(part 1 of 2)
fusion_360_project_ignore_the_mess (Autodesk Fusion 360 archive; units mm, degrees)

design "carcasa pantallita" references "ESP32-C3 supermini v5"
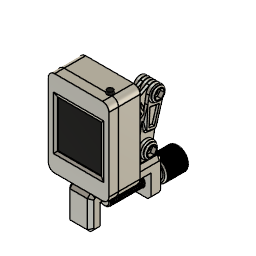
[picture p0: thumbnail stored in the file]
sketch "pantalla frente" plane through (0, 0, 0) normal (0, 1, 0) x axis (1, 0, 0)
  line L1 (29.45, 0) -> (0, 0)
  line L2 (29.45, -37.15) -> (29.45, 0)
  line L3 (0, -37.15) -> (29.45, -37.15)
  line L4 (0, 0) -> (0, -37.15)
  line L5 (28.45, -35.55) -> (1, -35.55)
  line L6 (28.45, -6.2) -> (28.45, -35.55)
  line L7 (1, -6.2) -> (28.45, -6.2)
  line L8 (1, -35.55) -> (1, -6.2)
  line L9 (30.7, -41.25) -> (-0.9, -41.25)
  line L10 (30.7, 3.05) -> (30.7, -41.25)
  line L11 (-0.9, 3.05) -> (30.7, 3.05)
  line L12 (-0.9, -41.25) -> (-0.9, 3.05)
  line L13 (14.9, -37.15) -> (14.9, -41.25)
  circle C1 centre (28.75, -39.5) radius 1.1
  circle C2 centre (1.05, -39.5) radius 1.1
  point P1 (0, 0)
  point P2 (0, 0)
  point P15 (14.9, -41.25)
  point P16 (14.9, -37.15)
  point P4 (29.45, -37.15)
  point P5 (0, -37.15)
  point P10 (-0.9, -41.25)
  point P11 (30.7, -41.25)
  point P13 (-0.9, 3.05)
  point P14 (28.75, -39.5)
  horizontal L1
  vertical L2
  horizontal L3
  vertical L4
  coincident P1 P2
  horizontal L5
  vertical L6
  horizontal L7
  vertical L8
  horizontal L9
  vertical L10
  horizontal L11
  vertical L12
  midpoint L9 P15
  coincident L3 P16
  perpendicular L3 L13
  symmetric C1 L13 C2
  dimension "d1" distance P4 P5 = 29.45
  dimension "d2" distance P2 P5 = 37.15
  dimension "d3" distance L3 L5 = 1.6
  dimension "d4" distance L2 L6 = 1
  dimension "d5" distance L4 L8 = 1
  dimension "d6" distance L1 L7 = 6.2
  dimension "d7" distance P10 P11 = 31.6
  dimension "d8" distance P10 P13 = 44.3
  dimension "d9" distance L3 L9 = 4.1
  dimension "d10" distance L4 L12 = 0.9
  dimension "d11" distance L9 P14 = 1.75 (= "1.1 mm + 0.65 mm")
  dimension "d12" distance L10 P14 = 1.95 (= "1.1 mm + 0.85 mm")
  dimension "d13" diameter C1 = 2.2
sketch "pantalla atras" plane through (0, 0, 0) normal (0, 1, 0) x axis (1, 0, 0)
  line L1 (30.7, -41.25) -> (-0.9, -41.25)
  line L2 (30.7, 3.05) -> (30.7, -41.25)
  line L3 (-0.9, -41.25) -> (-0.9, 3.05)
  line L4 (-0.9, 3.05) -> (30.7, 3.05)
  line L5 (14.15, -17.05) -> (1.2, -17.05)
  line L6 (14.15, -7.75) -> (14.15, -17.05)
  line L7 (1.2, -7.75) -> (14.15, -7.75)
  line L8 (1.2, -17.05) -> (1.2, -7.75)
  line L9 (0.6, 0.15) -> (28.8, 0.15)
  line L10 (0.6, 2.65) -> (0.6, 0.15)
  line L11 (28.8, 2.65) -> (0.6, 2.65)
  line L12 (28.8, 0.15) -> (28.8, 2.65)
  circle C1 centre (28.75, -39.5) radius 1.1
  circle C2 centre (1.05, -39.5) radius 1.1
  point P8 (1.2, -17.05)
  point P9 (14.15, -17.05)
  horizontal L5
  vertical L6
  horizontal L7
  vertical L8
  horizontal L9
  vertical L10
  horizontal L11
  vertical L12
  dimension "d14" distance L3 L8 = 2.1
  dimension "d15" distance P8 P9 = 12.95
  dimension "d16" distance L5 L7 = 9.3
  dimension "d17" distance L1 L5 = 24.2
  dimension "d18" distance L3 L10 = 1.5
  dimension "d19" distance L2 L12 = 1.9
  dimension "d20" distance L4 L11 = 0.4
  dimension "d21" distance L9 L11 = 2.5
extrude "Extrude1" new body sketch "pantalla frente" profile of L1 L2 L3 L4 L5 L6 L7 L8 L9 L10 L11 L12 C1 C2 along normal blind 1.65
extrude "Extrude2" add sketch "pantalla frente" profile of L1 L2 L3 L4 L5 L6 L7 L8 against normal blind 3.3
extrude "Extrude3" sketch "pantalla frente" profile of L5 L6 L7 L8 blind 0.01
extrude "Extrude4" sketch "pantalla atras" profile of L5 L6 L7 L8 blind 2.6
extrude "Extrude5" sketch "pantalla atras" profile of L9 L10 L11 L12 blind 2.4
sketch "cover frente" plane through (0, 0, 0) normal (0, 1, 0) x axis (1, 0, 0)
  line L1 (-4.25, -47.8) -> (33.7, -47.8)
  line L2 (-4.25, 6.05) -> (-4.25, -47.8)
  line L3 (33.7, 6.05) -> (-4.25, 6.05)
  line L4 (33.7, -47.8) -> (33.7, 6.05)
  line L5 (30.7, -41.25) -> (-0.9, -41.25)
  line L6 (30.7, 3.05) -> (30.7, -41.25)
  line L7 (-0.9, 3.05) -> (30.7, 3.05)
  line L8 (-0.9, -41.25) -> (-0.9, 3.05)
  line L9 (1, -35.55) -> (1, -6.2)
  line L10 (28.45, -35.55) -> (1, -35.55)
  line L11 (1, -6.2) -> (28.45, -6.2)
  line L12 (28.45, -6.2) -> (28.45, -35.55)
  horizontal L1
  vertical L2
  horizontal L3
  vertical L4
  dimension "d35" distance L4 L6 = 3
  dimension "d37" distance L3 L7 = 3
  dimension "d39" distance L1 L10 = 12.25
  dimension "d40" distance L2 L9 = 5.25
extrude "Extrude6" sketch "cover frente" profile of L1 L2 L3 L4 L9 L10 L11 L12 to an object from offset -1
combine "Combine1"
offset_faces "OffsetFaces1" distance -0.2
offset_faces "OffsetFaces2" distance -0.2
offset_faces "OffsetFaces3" distance -0.2
offset_faces "OffsetFaces4" distance -0.2
offset_faces "OffsetFaces5" distance -0.2
offset_faces "OffsetFaces6" distance -0.2
chamfer "Chamfer1" distance 0.6 distance 2
sketch "Sketch5" plane through (0, 0, 0) normal (0, 1, 0) x axis (1, 0, 0)
  line L1 (-4.25, -47.8) -> (33.7, -47.8)
  line L2 (33.7, -47.8) -> (33.7, 6.05)
  line L3 (-4.25, 6.05) -> (-4.25, -47.8)
  line L4 (33.7, 6.05) -> (-4.25, 6.05)
  line L5 (-4.25, -5.95) -> (33.7, -5.95)
  line L6 (30.9, -41.45) -> (30.9, 3.25)
  line L7 (-1.1, -41.45) -> (30.9, -41.45)
  line L8 (-1.1, 3.25) -> (-1.1, -41.45)
  line L9 (30.9, 3.25) -> (-1.1, 3.25)
  point P6 (33.7, -5.95)
  point P7 (-4.25, -5.95)
  point P8 (30.7, 3.05)
  coincident L2 P6
  coincident L3 P7
  perpendicular L3 L5
  dimension "d52" distance L5 P8 = 9
extrude "Extrude7" sketch "Sketch5" to an object offset 3
extrude "Extrude8" cut sketch "Sketch5" profile of L5 L6 L7 L8 L9 to an object offset -1
extrude "Extrude9" add of existing geometry blind 14 from offset 8
sketch "Sketch6" plane through (0, 1.65, 0) normal (0, -1, 0) x axis (1, 0, 0)
  line L1 (30.9, -3.25) -> (30.9, 19.45)
  line L2 (-1.1, -3.25) -> (30.9, -3.25)
  line L3 (-1.1, 19.45) -> (-1.1, -3.25)
  line L4 (30.9, 19.45) -> (-1.1, 19.45)
  line L5 (-1.1, 33.45) -> (30.9, 33.45)
  line L6 (-1.1, 41.45) -> (-1.1, 33.45)
  line L7 (30.9, 41.45) -> (-1.1, 41.45)
  line L8 (30.9, 33.45) -> (30.9, 41.45)
  line L9 (-4.25, -6.05) -> (-4.25, 47.8)
  line L10 (33.7, -6.05) -> (-4.25, -6.05)
  line L11 (33.7, 47.8) -> (33.7, -6.05)
  line L12 (-4.25, 47.8) -> (33.7, 47.8)
  line L13 (30.9, 19.45) -> (30.9, 33.45)
  line L14 (-1.1, 19.45) -> (-1.1, 33.45)
  line L15 (8.9, 19.45) -> (8.9, 33.45)
  line L16 (20.9, 19.45) -> (20.9, 33.45)
  line L17 (32.9, -5.25) -> (-3.45, -5.25)
  line L18 (32.9, 47) -> (32.9, -5.25)
  line L19 (-3.45, 47) -> (32.9, 47)
  line L20 (-3.45, -5.25) -> (-3.45, 47)
  point P6 (30.9, 33.45)
  point P14 (30.9, 33.45)
  point P2 (30.9, 19.45)
  point P15 (30.9, 19.45)
  point P7 (-1.1, 33.45)
  point P16 (-1.1, 33.45)
  point P5 (-1.1, 19.45)
  point P17 (-1.1, 19.45)
  point P18 (8.9, 33.45)
  point P19 (8.9, 19.45)
  point P20 (20.9, 33.45)
  point P21 (20.9, 19.45)
  coincident P6 P14
  coincident P2 P15
  coincident P7 P16
  coincident P5 P17
  coincident L5 P18
  coincident L4 P19
  perpendicular L4 L15
  coincident L5 P20
  coincident L4 P21
  perpendicular L4 L16
  dimension "d71" distance L13 L16 = 10
  dimension "d72" distance L14 L15 = 10
  dimension "d77" = -0.8
extrude "Extrude10" cut sketch "Sketch6" profile of L4 L5 L13 L14 against normal blind 0.2
extrude "Extrude11" cut of existing geometry blind -0.925 (= "( -1.65 / 2 ) * 1 mm - 0.1 mm")
extrude "Extrude12" new body of existing geometry to an object
combine "Combine2"
combine "Combine3"
offset_faces "OffsetFaces7" distance -0.1
chamfer "Chamfer2" distance 2 distance 2
extrude "Extrude13" cut sketch "Sketch6" profile of L4 L5 L15 L16 to an object
chamfer "Chamfer3" distance 0.4 distance 1
extrude "Extrude14" add sketch "Sketch6" profile of L1 L2 L3 L6 L7 L8 L13 L14 L17 L18 L19 L20 along normal blind 1.4
fillet "Fillet3" radius 4
combine "Combine4"
offset_faces "OffsetFaces8" distance -0.1
offset_faces "OffsetFaces9" distance -0.1
fillet "Fillet4" radius 4
sketch "Sketch7" plane through (0, 7.05, 0) normal (0, 1, 0) x axis (-1, 0, 0)
  line L1 (4.25, 43.8) -> (4.25, -2.05)
  line L2 (-29.7, 47.8) -> (0.25, 47.8)
  line L3 (-33.7, -2.05) -> (-33.7, 43.8)
  line L4 (0.25, -6.05) -> (-29.7, -6.05)
  line L5 (4.25, 20.875) -> (-33.7, 20.875)
  line L6 (-14.725, 20.875) -> (-14.725, 47.8)
  line L7 (-14.725, -6.05) -> (-14.725, 20.875)
  line L8 (4.25, 17.875) -> (-33.7, 17.875)
  line L9 (4.25, 23.875) -> (-33.7, 23.875)
  line L10 (-11.725, 47.8) -> (-11.725, -6.05)
  line L11 (-17.725, -6.05) -> (-17.725, 47.8)
  arc A1 centre (0.25, -2.05) radius 4 clockwise from (4.25, -2.05) to (0.25, -6.05)
  arc A2 centre (0.25, 43.8) radius 4 clockwise from (0.25, 47.8) to (4.25, 43.8)
  arc A3 centre (-29.7, 43.8) radius 4 clockwise from (-33.7, 43.8) to (-29.7, 47.8)
  arc A4 centre (-29.7, -2.05) radius 4 clockwise from (-29.7, -6.05) to (-33.7, -2.05)
  circle C1 centre (-14.725, 20.875) radius 3
  circle C2 centre (-14.725, 20.875) radius 9
  circle C3 centre (-14.725, 20.875) radius 12
  circle C4 centre (-14.725, 20.875) radius 10.5
  arc A5 centre (-10.225, 30.3618) radius 1.5 clockwise from (-10.8679, 29.0066) to (-9.5821, 31.7171)
  arc A6 centre (-5.2382, 25.375) radius 1.5 clockwise from (-3.8829, 26.0179) to (-6.5934, 24.7321)
  arc A7 centre (-19.225, 30.3618) radius 1.5 clockwise from (-19.8679, 31.7171) to (-18.5821, 29.0066)
  arc A8 centre (-5.2382, 16.375) radius 1.5 clockwise from (-6.5934, 17.0179) to (-3.8829, 15.7321)
  arc A9 centre (-24.2118, 16.375) radius 1.5 clockwise from (-25.5671, 15.7321) to (-22.8566, 17.0179)
  arc A10 centre (-24.2118, 25.375) radius 1.5 clockwise from (-22.8566, 24.7321) to (-25.5671, 26.0179)
  arc A11 centre (-19.225, 11.3882) radius 1.5 clockwise from (-18.5821, 12.7434) to (-19.8679, 10.0329)
  arc A12 centre (-10.225, 11.3882) radius 1.5 clockwise from (-9.5821, 10.0329) to (-10.8679, 12.7434)
  circle C5 centre (-14.725, 20.875) radius 7
  circle C6 centre (-14.725, 20.875) radius 14
  point P14 (-33.7, 20.875)
  point P15 (4.25, 20.875)
  point P16 (-14.725, 47.8)
  point P17 (-14.725, 20.875)
  point P18 (-14.725, -6.05)
  point P19 (-14.725, 20.875)
  point P20 (-14.725, 20.875)
  point P22 (-33.7, 17.875)
  point P23 (4.25, 17.875)
  point P24 (-33.7, 23.875)
  point P25 (4.25, 23.875)
  point P26 (-11.725, -6.05)
  point P27 (-11.725, 47.8)
  point P28 (-17.725, 47.8)
  point P29 (-17.725, -6.05)
  point P34 (-9.5821, 31.7171)
  point P35 (-10.8679, 29.0066)
  point P36 (-3.8829, 26.0179)
  point P37 (-6.5934, 24.7321)
  point P38 (-19.8679, 31.7171)
  point P39 (-18.5821, 29.0066)
  point P41 (-6.5934, 17.0179)
  point P42 (-3.8829, 15.7321)
  point P48 (-25.5671, 26.0179)
  point P47 (-22.8566, 24.7321)
  point P45 (-22.8566, 17.0179)
  point P44 (-25.5671, 15.7321)
  point P53 (-9.5821, 10.0329)
  point P54 (-10.8679, 12.7434)
  point P51 (-19.8679, 10.0329)
  point P50 (-18.5821, 12.7434)
  midpoint L3 P14
  midpoint L1 P15
  midpoint L2 P16
  midpoint L5 P17
  midpoint L4 P18
  coincident P17 P19
  coincident P17 P20
  concentric C2 C3
  coincident L3 P22
  coincident L1 P23
  perpendicular L1 L8
  coincident L3 P24
  coincident L1 P25
  perpendicular L1 L9
  coincident L4 P26
  coincident L2 P27
  perpendicular L2 L10
  coincident L2 P28
  coincident L4 P29
  perpendicular L4 L11
  concentric C1 C4
  tangent C3 A6
  tangent L9 A6
  tangent C2 A5
  tangent C2 A7
  tangent L11 A7
  tangent L10 A5
  coincident C3 P34
  coincident C2 P35
  coincident C3 P36
  coincident C2 P37
  coincident C3 P38
  coincident C2 P39
  tangent C3 A8
  tangent L8 A8
  coincident C2 P41
  coincident C3 P42
  symmetric L7 P36 P48
  symmetric L7 A6 A10
  symmetric L7 P37 P47
  symmetric L7 P41 P45
  symmetric L7 A8 A9
  symmetric L7 P42 P44
  symmetric L5 P34 P53
  symmetric L5 A5 A12
  symmetric L5 P35 P54
  symmetric L5 P38 P51
  symmetric L5 A7 A11
  symmetric L5 P39 P50
  concentric C3 C5
  concentric C3 C6
  dimension "d90" diameter C1 = 6
  dimension "d95" diameter C2 = 18
  dimension "d96" diameter C3 = 24
  dimension "d97" distance L5 L9 = 3
  dimension "d98" distance L5 L8 = 3
  dimension "d99" distance L7 L11 = 3
  dimension "d100" distance L7 L10 = 3
  dimension "d101" diameter C4 = 21
  dimension "d104" diameter C5 = 14
  dimension "d105" diameter C6 = 28
extrude "Extrude15" cut sketch "Sketch7" profile of C1 to an object
fillet "Fillet5" radius 0.4
extrude "Extrude16" cut sketch "Sketch7" profile of C2 C3 A6 A5 A7 A8 A9 A10 A11 A12 to an object
extrude "Extrude17" sketch "Sketch7" profile of C2 C3 L8 L9 L10 L11 A6 A5 A7 A8 A9 A10 A11 A12 C5 C6 to an object
delete_face "DeleteFace1"
delete_face "DeleteFace2"
delete_face "DeleteFace3"
sketch "Sketch8" plane through (0, 7.05, 0) normal (0, 1, 0) x axis (-1, 0, 0)
  line L1 (4.25, 43.8) -> (4.25, -2.05)
  line L2 (-29.7, 47.8) -> (0.25, 47.8)
  line L3 (-33.7, -2.05) -> (-33.7, 43.8)
  line L4 (0.25, -6.05) -> (-29.7, -6.05)
  line L5 (-9.725, 16.875) -> (-19.725, 16.875)
  line L6 (-9.725, 6.875) -> (-9.725, 16.875)
  line L7 (-19.725, 6.875) -> (-9.725, 6.875)
  line L8 (-19.725, 16.875) -> (-19.725, 6.875)
  line L9 (-14.725, 5.875) -> (-14.725, 20.875)
  line L10 (-17.725, 6.875) -> (-17.725, 16.875)
  line L11 (-15.725, 6.875) -> (-15.725, 16.875)
  line L12 (-11.725, 6.875) -> (-11.725, 16.875)
  line L13 (-13.725, 6.875) -> (-13.725, 16.875)
  arc A1 centre (-14.725, 20.875) radius 9 clockwise from (-18.5821, 12.7434) to (-22.8566, 17.0179)
  arc A2 centre (-19.225, 11.3882) radius 1.5 clockwise from (-18.5821, 12.7434) to (-19.8679, 10.0329)
  arc A3 centre (-14.725, 20.875) radius 12 clockwise from (-19.8679, 10.0329) to (-25.5671, 15.7321)
  arc A4 centre (-24.2118, 16.375) radius 1.5 clockwise from (-25.5671, 15.7321) to (-22.8566, 17.0179)
  arc A5 centre (-14.725, 20.875) radius 9 clockwise from (-22.8566, 24.7321) to (-18.5821, 29.0066)
  arc A6 centre (-24.2118, 25.375) radius 1.5 clockwise from (-22.8566, 24.7321) to (-25.5671, 26.0179)
  arc A7 centre (-14.725, 20.875) radius 12 clockwise from (-25.5671, 26.0179) to (-19.8679, 31.7171)
  arc A8 centre (-19.225, 30.3618) radius 1.5 clockwise from (-19.8679, 31.7171) to (-18.5821, 29.0066)
  arc A9 centre (-14.725, 20.875) radius 9 clockwise from (-6.5934, 17.0179) to (-10.8679, 12.7434)
  arc A10 centre (-5.2382, 16.375) radius 1.5 clockwise from (-6.5934, 17.0179) to (-3.8829, 15.7321)
  arc A11 centre (-14.725, 20.875) radius 12 clockwise from (-3.8829, 15.7321) to (-9.5821, 10.0329)
  arc A12 centre (-10.225, 11.3882) radius 1.5 clockwise from (-9.5821, 10.0329) to (-10.8679, 12.7434)
  arc A13 centre (-14.725, 20.875) radius 9 clockwise from (-10.8679, 29.0066) to (-6.5934, 24.7321)
  arc A14 centre (-10.225, 30.3618) radius 1.5 clockwise from (-10.8679, 29.0066) to (-9.5821, 31.7171)
  arc A15 centre (-14.725, 20.875) radius 12 clockwise from (-9.5821, 31.7171) to (-3.8829, 26.0179)
  arc A16 centre (-5.2382, 25.375) radius 1.5 clockwise from (-3.8829, 26.0179) to (-6.5934, 24.7321)
  circle C1 centre (-14.725, 20.875) radius 3
  arc A17 centre (0.25, -2.05) radius 4 clockwise from (4.25, -2.05) to (0.25, -6.05)
  arc A18 centre (0.25, 43.8) radius 4 clockwise from (0.25, 47.8) to (4.25, 43.8)
  arc A19 centre (-29.7, 43.8) radius 4 clockwise from (-33.7, 43.8) to (-29.7, 47.8)
  arc A20 centre (-29.7, -2.05) radius 4 clockwise from (-29.7, -6.05) to (-33.7, -2.05)
  circle C2 centre (-14.725, 20.875) radius 15
  circle C3 centre (-14.725, 20.875) radius 3
  point P4 (-14.725, 20.875)
  point P45 (-14.725, 20.875)
  point P46 (-14.725, 5.875)
  point P47 (-17.725, 16.875)
  point P48 (-17.725, 6.875)
  point P49 (-15.725, 16.875)
  point P50 (-15.725, 6.875)
  point P51 (-11.725, 16.875)
  point P52 (-11.725, 6.875)
  point P53 (-13.725, 16.875)
  point P54 (-13.725, 6.875)
  point P39 (-14.725, 20.875)
  concentric A1 C2
  concentric A1 C3
  horizontal L5
  vertical L6
  horizontal L7
  vertical L8
  coincident P4 P45
  coincident C2 P46
  perpendicular L7 L9
  coincident L5 P47
  coincident L7 P48
  perpendicular L7 L10
  coincident L5 P49
  coincident L7 P50
  perpendicular L5 L11
  coincident L5 P51
  coincident L7 P52
  perpendicular L7 L12
  coincident L5 P53
  coincident L7 P54
  perpendicular L7 L13
  dimension "d109" diameter C2 = 30
  dimension "d110" diameter C3 = 6
  dimension "d111" distance L8 L9 = 5
  dimension "d112" distance L6 L9 = 5
  dimension "d113" distance L5 L7 = 10
  dimension "d114" distance P39 L5 = 4
  dimension "d118" distance L8 L10 = 2
  dimension "d119" distance L10 L11 = 2
  dimension "d120" distance L6 L12 = 2
  dimension "d121" distance L12 L13 = 2
extrude "Extrude18" new body sketch "Sketch8" profile of A1 A2 A9 A12 L5 L6 L7 L8 L10 L11 L12 L13 blind 10 from offset 2 bodies "mount"
sketch "Sketch9" plane through (19.725, 0, 0) normal (1, 0, 0) x axis (0, 1, 0)
  line L1 (9.05, 6.875) -> (9.05, 16.875)
  line L2 (19.05, 6.875) -> (9.05, 6.875)
  line L3 (19.05, 16.875) -> (19.05, 6.875)
  line L4 (9.05, 16.875) -> (19.05, 16.875)
  line L5 (19.05, 6.875) -> (9.05, 16.875)
  line L6 (19.05, 16.875) -> (9.05, 6.875)
  line L7 (14.05, 15.0504) -> (16.8, 13.4627)
  line L8 (11.3, 13.4627) -> (14.05, 15.0504)
  line L9 (11.3, 10.2873) -> (11.3, 13.4627)
  line L10 (14.05, 8.6996) -> (11.3, 10.2873)
  line L11 (16.8, 10.2873) -> (14.05, 8.6996)
  line L12 (16.8, 13.4627) -> (16.8, 10.2873)
  circle C1 centre (14.05, 11.875) radius 1.65
  circle C2 centre (14.05, 11.875) radius 4.2
  point P2 (9.05, 16.875)
  point P6 (9.05, 16.875)
  point P4 (19.05, 6.875)
  point P7 (19.05, 6.875)
  point P3 (9.05, 6.875)
  point P8 (9.05, 6.875)
  point P5 (19.05, 16.875)
  point P9 (19.05, 16.875)
  point P16 (14.05, 11.875)
  point P17 (14.05, 11.875)
  coincident P2 P6
  coincident P4 P7
  coincident P3 P8
  coincident P5 P9
  midpoint L5 P16
  parallel L3 L12
  coincident P16 P17
  concentric C1 C2
  dimension "d122" distance P16 L12 = 2.75 (= "( ( 5.5 ) / 2 ) * 1 mm")
  dimension "d123" diameter C1 = 3.3
  dimension "d130" diameter C2 = 8.4
extrude "Extrude19" cut sketch "Sketch9" profile of C1 to an object
offset_faces "OffsetFaces10" distance -0.1
offset_faces "OffsetFaces11" distance -0.1
offset_faces "OffsetFaces12" distance -0.1
offset_faces "OffsetFaces13" distance -0.1
extrude "Extrude20" cut sketch "Sketch9" profile of L7 L8 L9 L10 L11 L12 C1 against normal blind 0.6
extrude "Extrude21" add sketch "Sketch9" profile of L7 L8 L9 L10 L11 L12 C2 along normal blind 2
fillet "Fillet6" radius 0.8
fillet "Fillet7" radius 5
extrude "Extrude22" add sketch "Sketch8" profile of A1 A2 A3 A4 A5 A6 A7 A8 A9 A10 A11 A12 A13 A14 A15 A16 C1 C2 C3 L5 L6 L7 L8 L10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 along normal blind 2
sketch "Sketch10" plane through (0, 7.05, 0) normal (0, -1, 0) x axis (1, 0, 0)
  line L1 (23.0689, 29.2189) -> (14.725, 20.875)
  line L2 (26.525, 20.875) -> (14.725, 20.875)
  circle C1 centre (14.725, 20.875) radius 3
  circle C2 centre (14.725, 20.875) radius 15
  arc A1 centre (10.225, 30.3618) radius 1.5 clockwise from (9.5821, 31.7171) to (10.8679, 29.0066)
  circle C3 centre (14.725, 20.875) radius 12
  circle C4 centre (14.725, 20.875) radius 9
  arc A2 centre (5.2382, 25.375) radius 1.5 clockwise from (6.5934, 24.7321) to (3.8829, 26.0179)
  arc A3 centre (5.2382, 16.375) radius 1.5 clockwise from (3.8829, 15.7321) to (6.5934, 17.0179)
  arc A4 centre (10.225, 11.3882) radius 1.5 clockwise from (10.8679, 12.7434) to (9.5821, 10.0329)
  arc A5 centre (19.225, 11.3882) radius 1.5 clockwise from (19.8679, 10.0329) to (18.5821, 12.7434)
  arc A6 centre (24.2118, 16.375) radius 1.5 clockwise from (22.8566, 17.0179) to (25.5671, 15.7321)
  arc A7 centre (24.2118, 25.375) radius 1.5 clockwise from (25.5671, 26.0179) to (22.8566, 24.7321)
  arc A8 centre (19.225, 30.3618) radius 1.5 clockwise from (18.5821, 29.0066) to (19.8679, 31.7171)
  circle C5 centre (14.725, 20.875) radius 9.2
  circle C6 centre (14.725, 20.875) radius 11.8
  arc A9 centre (24.2118, 25.375) radius 1.3 clockwise from (25.3864, 25.9321) to (23.0373, 24.8179)
  arc A10 centre (19.225, 30.3618) radius 1.3 clockwise from (18.6679, 29.1873) to (19.7821, 31.5364)
  arc A11 centre (5.2382, 16.375) radius 1.3 clockwise from (4.0636, 15.8179) to (6.4127, 16.9321)
  arc A12 centre (10.225, 11.3882) radius 1.3 clockwise from (10.7821, 12.5627) to (9.6679, 10.2136)
  point P30 (14.725, 20.875)
  point P31 (14.725, 20.875)
  point P32 (23.0689, 29.2189)
  concentric C3 C5
  concentric C5 C6
  horizontal L2
  coincident P30 P31
  coincident C6 P32
  dimension "d141" diameter C5 = 18.4
  dimension "d142" diameter C6 = 23.6 (= "24 mm - 0.4 mm")
  dimension "d143" angle L1 L2 = 45
  dimension "d144" = -0.2
  dimension "d145" = -0.2
  dimension "d146" = -0.2
  dimension "d147" = -0.2
extrude "Extrude23" new body sketch "Sketch10" profile of C5 C6 A9 A10 A11 A12 blind 1.4 from offset 1.2
move "Move1" RotateAngle -32
sketch "Sketch11" plane through (0, 7.05, 0) normal (0, -1, 0) x axis (1, 0, 0)
  circle C1 centre (14.725, 20.875) radius 3
  circle C2 centre (14.725, 20.875) radius 15
  arc A1 centre (19.225, 30.3618) radius 1.3 clockwise from (18.6679, 29.1873) to (19.7821, 31.5364)
  arc A2 centre (10.225, 11.3882) radius 1.3 clockwise from (10.7821, 12.5627) to (9.6679, 10.2136)
  arc A3 centre (20.3857, 29.7185) radius 1.3 clockwise from (21.0865, 30.8134) to (19.6848, 28.6236)
  arc A4 centre (14.725, 20.875) radius 11.8 clockwise from (13.364, 32.5963) to (21.0865, 30.8134)
  arc A5 centre (13.514, 31.3049) radius 1.3 clockwise from (13.6639, 30.0136) to (13.364, 32.5963)
  arc A6 centre (14.725, 20.875) radius 9.2 clockwise from (13.6639, 30.0136) to (19.6848, 28.6236)
  arc A7 centre (9.0643, 12.0315) radius 1.3 clockwise from (8.3635, 10.9366) to (9.7652, 13.1264)
  arc A8 centre (14.725, 20.875) radius 11.8 clockwise from (16.086, 9.1537) to (8.3635, 10.9366)
  arc A9 centre (15.936, 10.4451) radius 1.3 clockwise from (15.7861, 11.7364) to (16.086, 9.1537)
  arc A10 centre (14.725, 20.875) radius 9.2 clockwise from (15.7861, 11.7364) to (9.7652, 13.1264)
extrude "Extrude24" add sketch "Sketch11" profile of A1 A2 A3 A4 A6 A7 A8 A10 to an object
chamfer "Chamfer4" distance 1 distance 1
offset_faces "OffsetFaces14" distance -0.1
chamfer "Chamfer5" distance 0.8 distance 0.4
sketch "Sketch12" plane through (0, 0, 0) normal (0, 1, 0) x axis (1, 0, 0)
  line L1 (85.8406, 9.05) -> (-58.1093, 9.05)
  line L2 (85.8406, 63.6285) -> (85.8406, 9.05)
  line L3 (-58.1093, 63.6285) -> (85.8406, 63.6285)
  line L4 (-58.1093, 9.05) -> (-58.1093, 63.6285)
  line L5 (29.7, 6.05) -> (-0.25, 6.05)
  horizontal L1
  vertical L2
  horizontal L3
  vertical L4
  dimension "d159" distance L1 L5 = 3
sketch "Sketch13" plane through (0, 0, 0) normal (0, 0, 1) x axis (1, 0, 0)
  line L1 (30.5, 5.65) -> (24.5, 5.65)
  line L2 (30.5, -0.35) -> (30.5, 5.65)
  line L3 (24.5, -0.35) -> (30.5, -0.35)
  line L4 (24.5, 5.65) -> (24.5, -0.35)
  line L5 (-4.25, 1.65) -> (-3.45, 1.65)
  line L6 (32.9, 1.65) -> (33.7, 1.65)
  line L7 (-0.25, 7.05) -> (29.7, 7.05)
  line L8 (33.7, 7.05) -> (29.7, 7.05)
  line L9 (33.7, 1.65) -> (33.7, 7.05)
  line L10 (-4.25, 7.05) -> (-4.25, 1.65)
  line L11 (-0.25, 7.05) -> (-4.25, 7.05)
  line L12 (-3.45, 1.65) -> (-3.45, 0.25)
  line L13 (32.9, 0.25) -> (32.9, 1.65)
  line L14 (28.9, 0.25) -> (32.9, 0.25)
  line L15 (28.9, 0.25) -> (0.55, 0.25)
  line L16 (-3.45, 0.25) -> (0.55, 0.25)
  line L17 (-0.25, 1.65) -> (-4.25, 1.65)
  line L18 (-4.25, -4.3) -> (-0.25, -4.3)
  line L19 (-4.25, 1.65) -> (-4.25, -4.3)
  line L20 (29.7, 1.65) -> (-0.25, 1.65)
  line L21 (29.7, -4.3) -> (-0.25, -4.3)
  line L22 (33.7, 1.65) -> (29.7, 1.65)
  line L23 (33.7, -4.3) -> (33.7, 1.65)
  line L24 (29.7, -4.3) -> (33.7, -4.3)
  line L25 (6.5934, 6.05) -> (10.8679, 6.05)
  line L26 (6.5934, 6.05) -> (3.7382, 6.05)
  line L27 (3.8829, 6.05) -> (9.5821, 6.05)
  line L28 (9.5821, 6.05) -> (11.725, 6.05)
  line L29 (18.125, 6.05) -> (11.325, 6.05)
  line L30 (-1.1, 6.05) -> (0.7977, 6.05)
  line L31 (30.9, 6.05) -> (-1.1, 6.05)
  line L32 (28.6523, 6.05) -> (30.9, 6.05)
  line L33 (20.9, 6.05) -> (28.725, 6.05)
  line L34 (30.9, 6.05) -> (20.9, 6.05)
  line L35 (30.9, 6.05) -> (25.85, 6.05)
  line L36 (3.1965, 6.05) -> (26.6035, 6.05)
  line L37 (3.95, 6.05) -> (-1.1, 6.05)
  line L38 (8.5712, 6.05) -> (-1.1, 6.05)
  line L39 (0.725, 6.05) -> (8.5712, 6.05)
  line L40 (25.5671, 6.05) -> (19.8679, 6.05)
  line L41 (25.7118, 6.05) -> (22.8566, 6.05)
  line L42 (22.8566, 6.05) -> (18.5821, 6.05)
  line L43 (17.725, 6.05) -> (19.8679, 6.05)
  line L44 (22.8566, 6.05) -> (18.5821, 6.05)
  line L45 (22.8566, 6.05) -> (25.7118, 6.05)
  line L46 (19.8679, 6.05) -> (25.5671, 6.05)
  line L47 (17.725, 6.05) -> (19.8679, 6.05)
  line L48 (10.8679, 6.05) -> (6.5934, 6.05)
  line L49 (9.5821, 6.05) -> (11.725, 6.05)
  line L50 (3.8829, 6.05) -> (9.5821, 6.05)
  line L51 (3.7382, 6.05) -> (6.5934, 6.05)
  line L52 (30.9, 5.3) -> (30.9, 6.05)
  line L53 (30.9, 2.85) -> (30.9, 6.05)
  line L54 (30.9, 1.85) -> (30.9, 2.85)
  line L55 (30.9, 2.85) -> (30.9, 1.85)
  line L56 (30.9, 6.05) -> (30.9, 2.85)
  line L57 (30.9, 0.25) -> (30.9, 6.05)
  line L58 (30.9, 6.05) -> (30.9, 0.25)
  line L59 (30.5, -0.35) -> (24.5, 5.65)
  line L60 (30.5, 5.65) -> (24.5, -0.35)
  circle C1 centre (27.5, 2.65) radius 1.75
  point P6 (27.5, 2.65)
  point P2 (24.5, 5.65)
  point P3 (30.5, 5.65)
  point P5 (24.5, -0.35)
  horizontal L1
  vertical L2
  horizontal L3
  vertical L4
  coincident P6 L60
  coincident P6 L59
  dimension "d160" distance P2 P3 = 6
  dimension "d161" distance P2 P5 = 6
  dimension "d162" diameter C1 = 3.5
  dimension "d163" distance L1 L31 = 0.4
  dimension "d164" distance L2 L56 = 0.4
extrude "Extrude25" sketch "Sketch13" profile of L1 L2 L3 L4 C1 L14 L15 L20 L22 blind 3.6 from offset -5 (= "-7 mm + 2 mm")
extrude "Extrude26" sketch "Sketch13" profile of C1 L20 to an object
extrude "Extrude27" cut of existing geometry to an object
offset_faces "OffsetFaces15" distance -0.1
extrude "Extrude28" sketch "Sketch13" profile of C1 L20 to an object
offset_faces "OffsetFaces16" distance -0.2
offset_faces "OffsetFaces17" distance -0.1
offset_faces "OffsetFaces18" distance -0.1
offset_faces "OffsetFaces19" distance -0.2
offset_faces "OffsetFaces20" distance -0.1
offset_faces "OffsetFaces21" distance -0.1
chamfer "Chamfer6" distance 0.2
chamfer "Chamfer7" distance 0.2
chamfer "Chamfer8" distance 0.2
delete_face "DeleteFace4"
chamfer "Chamfer9" distance 1
chamfer "Chamfer10" distance 0.2829
sketch "Sketch14" plane through (0, 0, 0) normal (1, 0, 0) x axis (0, 1, 0)
  line L1 (28.5, -14.05) -> (2.1, -14.05)
  line L2 (28.5, -30.05) -> (28.5, -14.05)
  line L3 (62.0785, -63.6285) -> (28.5, -30.05)
  line L4 (2.1, -63.6285) -> (62.0785, -63.6285)
  line L5 (33.5, -13.65) -> (33.5, -28.55)
  line L6 (1.7, -13.65) -> (33.5, -13.65)
  line L7 (1.7, -28.55) -> (1.7, -13.65)
  line L8 (-4.3, -28.55) -> (1.7, -28.55)
  line L9 (-4.3, -7.65) -> (-4.3, -28.55)
  line L10 (41.5, -7.65) -> (-4.3, -7.65)
  line L11 (41.5, -28.55) -> (41.5, -7.65)
  line L12 (33.5, -28.55) -> (41.5, -28.55)
  line L13 (28.5, -29.35) -> (2.1, -29.35)
  line L14 (2.1, -14.05) -> (2.1, -63.6285)
  line L15 (-4.3, -2.05) -> (-4.3, 43.8)
  line L16 (-4.3, -6.05) -> (1.65, -6.05)
  line L17 (1.65, -6.05) -> (7.05, -6.05)
  line L18 (8.1839, 6.875) -> (14.05, 6.875)
  curve K1 (9.05, 7.7983) -> (8.1839, 6.875)
  line L19 (9.05, 16.875) -> (9.05, 7.7983)
  line L20 (14.05, 16.875) -> (9.05, 16.875)
  line L21 (41.5, 2.35) -> (41.5, -7.65)
  line L22 (31.5, 2.35) -> (41.5, 2.35)
  line L23 (31.5, -7.65) -> (31.5, 2.35)
  line L24 (31.5, 2.35) -> (41.5, -7.65)
  line L25 (31.5, -7.65) -> (41.5, 2.35)
  line L26 (33.3246, -2.65) -> (34.9123, 0.1)
  line L27 (34.9123, -5.4) -> (33.3246, -2.65)
  line L28 (38.0877, -5.4) -> (34.9123, -5.4)
  line L29 (39.6754, -2.65) -> (38.0877, -5.4)
  line L30 (38.0877, 0.1) -> (39.6754, -2.65)
  line L31 (34.9123, 0.1) -> (38.0877, 0.1)
  arc A1 centre (14.05, 11.875) radius 5 clockwise from (14.05, 16.875) to (14.05, 6.875)
  circle C1 centre (14.05, 11.875) radius 1.65
  circle C2 centre (36.5, -2.65) radius 1.65
  circle C3 centre (36.5, -2.65) radius 4.2
  point P5 (62.0785, -63.6285)
  point P6 (62.0785, -63.6285)
  point P17 (28.5, -29.35)
  point P16 (2.1, -29.35)
  point P32 (31.5, -7.65)
  point P33 (36.5, -2.65)
  point P40 (36.5, -2.65)
  point P41 (36.5, -2.65)
  point P2 (2.1, -14.05)
  point P3 (28.5, -14.05)
  point P4 (28.5, -30.05)
  point P7 (2.1, -63.6285)
  point P14 (41.5, -7.65)
  point P30 (41.5, 2.35)
  point P31 (31.5, 2.35)
  perpendicular L1 L2
  coincident P5 P6
  parallel L2 L5
  perpendicular L5 L6
  perpendicular L6 L7
  perpendicular L7 L8
  perpendicular L8 L9
  perpendicular L7 L10
  perpendicular L10 L11
  perpendicular L11 L12
  coincident L2 P17
  perpendicular L2 L13
  perpendicular L1 L14
  coincident P16 L14
  perpendicular L4 L14
  collinear L9 L15
  perpendicular L10 L21
  perpendicular L21 L22
  coincident L10 P32
  perpendicular L10 L23
  midpoint L24 P33
  coincident P33 P40
  parallel L22 L31
  coincident P40 P41
  dimension "d189" distance P2 P3 = 26.4
  dimension "d190" distance P3 P4 = 16
  dimension "d191" angle L2 L3 = 135
  dimension "d192" distance L1 L13 = 15.3
  dimension "d193" distance L1 L6 = 0.4
  dimension "d195" distance L2 L5 = 5
  dimension "d196" distance L12 L13 = 0.8
  dimension "d197" distance L8 L13 = 0.8
  dimension "d198" distance L5 L11 = 8
  dimension "d199" distance L6 L10 = 6
  dimension "d200" distance L7 L9 = 6
  dimension "d201" distance L7 L14 = 0.4
  dimension "d202" distance P2 P7 = 49.5785 (= "54.5785262167 mm - 5 mm")
  dimension "d203" distance P14 P30 = 10
  dimension "d204" distance P30 P31 = 10
  dimension "d205" diameter C2 = 3.3
  dimension "d206" distance P40 L31 = 2.75 (= "( 5.5 / 2 ) * 1 mm")
  dimension "d207" diameter C3 = 8.4
extrude "Extrude29" sketch "Sketch14" profile of L5 L6 L7 L8 L9 L10 L11 L12 blind 15
chamfer "Chamfer11" distance 2
chamfer "Chamfer12" distance 2
chamfer "Chamfer13" distance 2
sketch "Sketch15" plane through (0, 41.5, 0) normal (0, 1, 0) x axis (-1, 0, 0)
  line L1 (-8.75, -26.55) -> (-8.75, -9.65)
  line L2 (2.25, -26.55) -> (-8.75, -26.55)
  line L3 (2.25, -9.65) -> (2.25, -26.55)
  line L4 (-8.75, -9.65) -> (2.25, -9.65)
  line L5 (-10.75, -13.65) -> (4.25, -13.65)
  line L6 (4.25, -13.65) -> (-10.75, -13.65)
  line L7 (2.25, -28.55) -> (-8.75, -28.55)
  line L8 (4.25, -10.4784) -> (4.25, -25.7216)
  line L9 (-10.75, -25.7216) -> (-10.75, -10.4784)
  line L10 (-3.25, -13.65) -> (-3.25, -28.55)
  line L11 (4.25, -21.1) -> (-3.25, -21.1)
  circle C1 centre (-3.25, -21.1) radius 4
  circle C2 centre (-3.25, -21.1) radius 7
  point P14 (-3.25, -28.55)
  point P15 (-3.25, -13.65)
  point P16 (-3.25, -21.1)
  point P17 (4.25, -21.1)
  point P18 (-3.25, -21.1)
  midpoint L7 P14
  midpoint L5 P15
  midpoint L10 P16
  coincident L8 P17
  perpendicular L8 L11
  coincident P16 P18
  concentric C1 C2
  dimension "d214" diameter C1 = 8
  dimension "d228" diameter C2 = 14
extrude "Extrude30" new body sketch "Sketch15" profile of C1 to an object offset 10 from offset 2 bodies "screw"
thread "Thread1" ThreadOffset 1.6 ThreadLength 30.2
chamfer "Chamfer14" distance 1
combine "Combine5"
offset_faces "OffsetFaces23" distance -0.1
fillet "Fillet8" radius 0.1
offset_faces "OffsetFaces24" distance -0.1
fillet "Fillet9" radius 0.1
extrude "Extrude31" sketch "Sketch15" profile of L1 L2 L3 C1 C2 blind 14
chamfer "Chamfer15" distance 1
fillet "Fillet10" radius 1
move "Move2"
sketch "Sketch16" plane through (0, 57.5, 0) normal (0, 1, 0) x axis (-1, 0, 0)
  line L1 (-2.9894, -21.1) -> (-14.725, -21.1)
  line L2 (-7.725, -24.4016) -> (-7.725, -17.8111)
  line L3 (-7.525, -21.1) -> (-7.725, -20.7)
  line L4 (-7.725, -21.5) -> (-7.525, -21.1)
  line L5 (-7.725, -21.5) -> (-7.925, -21.1)
  line L6 (-7.725, -20.7) -> (-7.925, -21.1)
  line L7 (-14.725, -14.1) -> (-14.725, -21.1)
  circle C1 centre (-14.725, -21.1) radius 7
  circle C2 centre (-14.725, -21.1) radius 7
  point P3 (-14.725, -21.1)
  point P4 (-14.725, -21.1)
  point P8 (-7.725, -20.7)
  point P9 (-7.525, -21.1)
  point P10 (-7.725, -21.5)
  point P11 (-7.925, -21.1)
  point P12 (-14.725, -21.1)
  point P13 (-14.725, -14.1)
  concentric C1 C2
  coincident P3 P4
  horizontal L1
  perpendicular L1 L2
  coincident L2 P8
  coincident L1 P9
  coincident L2 P10
  coincident L1 P11
  parallel L4 L6
  parallel L3 L5
  equal L3 L6
  equal L5 L6
  equal L4 L5
  equal L3 L4
  tangent C2 L2
  coincident P3 P12
  coincident C2 P13
  perpendicular L1 L7
  dimension "d235" distance P9 P11 = 0.4
  dimension "d236" diameter C2 = 14
  dimension "d237" distance P8 P10 = 0.8
coil_primitive "CoilPrimitive1" Diameter 14 SectionSize 0.4 TaperAngle 0 Revolutions 0.125 Height -13
sweep "Sweep1" sketch "Sketch16" TwistAngle 0 TaperAngle 0
work_plane "WorkPlane1" RotateAngle 90
mirror "Mirror1" mirrorStitchTolerance 0.1
sketch "Sketch20" plane through (14.725, 0, 0) normal (-1, 0, 0) x axis (0, -1, 0)
  line L1 (-11.7, -24.033) -> (-11.7, -18.167)
  line L2 (-11.7, -21.1) -> (-57.5, -21.1)
  point P2 (-57.5, -21.1)
  point P5 (-57.5, -21.1)
  point P6 (-11.7, -21.1)
  coincident P2 P5
  midpoint L1 P6
circular_pattern "C-Pattern1" countU 62 TotalAngle 360
extrude "Extrude32" cut of existing geometry blind -2
remove_body "RemoveBody1"
split "Split1"
copy_paste_bodies "CopyPasteBodies1"
move "Move3"
combine "Combine6"
combine "Combine7"
copy_paste_bodies "CopyPasteBodies2"
move "Move4"
offset_faces "OffsetFaces25" distance -0.1
combine "Combine9"
delete_face "DeleteFace5"
delete_face "DeleteFace6"
delete_face "DeleteFace7"
delete_face "DeleteFace8"
delete_face "DeleteFace9"
delete_face "DeleteFace10"
sketch "Sketch22" plane through (0, 0, 0) normal (1, 0, 0) x axis (0, 1, 0)
  line L1 (8.7528, 6.875) -> (14.05, 6.875)
  curve K1 (9.05, 7.1787) -> (8.7528, 6.875)
  line L2 (9.05, 16.875) -> (9.05, 7.1787)
  line L3 (14.05, 16.875) -> (9.05, 16.875)
  line L4 (29.5, -7.65) -> (39.5, -7.65)
  line L5 (29.5, -2.675) -> (29.5, -7.65)
  line L6 (39.5, -7.65) -> (39.5, -2.675)
  line L7 (39.5, -7.65) -> (-2.3, -7.65)
  line L8 (9.05, 7.1787) -> (9.05, 34.875)
  line L9 (14.05, 11.875) -> (34.5, -2.675)
  line L10 (39.348, 25.785) -> (24.275, 4.6)
  line L11 (14.05, 11.875) -> (39.348, 25.785)
  line L12 (34.5, -2.675) -> (39.348, 25.785)
  line L13 (34.5, 11.875) -> (34.5, -2.675)
  line L14 (34.5, 11.875) -> (14.05, 11.875)
  line L15 (43.8826, 25.0126) -> (39.348, 25.785)
  line L16 (34.8133, 26.5575) -> (39.348, 25.785)
  line L17 (39.0347, -3.4475) -> (43.8826, 25.0126)
  line L18 (34.5, -2.675) -> (39.0347, -3.4475)
  line L19 (29.9653, -1.9025) -> (34.5, -2.675)
  line L20 (34.8133, 26.5575) -> (29.9653, -1.9025)
  line L21 (30.9057, 3.6179) -> (39.9751, 2.073)
  line L22 (33.8729, 21.037) -> (42.9423, 19.4921)
  line L23 (29.5, -2.675) -> (34.5, -2.675)
  arc A1 centre (14.05, 11.875) radius 5 clockwise from (14.05, 16.875) to (14.05, 6.875)
  circle C1 centre (14.05, 11.875) radius 1.65
  arc A2 centre (34.5, -2.675) radius 5 clockwise from (29.5, -2.675) to (39.5, -2.675)
  circle C2 centre (34.5, -2.675) radius 1.65
  circle C3 centre (39.348, 25.785) radius 1.65
  circle C4 centre (39.348, 25.785) radius 4.6
  circle C5 centre (14.05, 11.875) radius 4.6
  circle C6 centre (34.5, -2.675) radius 4.6
  point P12 (34.5, -2.675)
  point P17 (34.5, -2.675)
  point P7 (14.05, 11.875)
  point P18 (14.05, 11.875)
  point P19 (24.275, 4.6)
  point P20 (39.348, 25.785)
  point P22 (39.348, 25.785)
  point P25 (34.5, -2.675)
  point P26 (39.348, 25.785)
  point P27 (43.8826, 25.0126)
  point P28 (39.348, 25.785)
  point P29 (34.8133, 26.5575)
  point P30 (39.0347, -3.4475)
  point P31 (34.5, -2.675)
  point P32 (34.5, -2.675)
  point P33 (29.9653, -1.9025)
  point P34 (39.9751, 2.073)
  point P35 (30.9057, 3.6179)
  point P36 (42.9423, 19.4921)
  point P37 (33.8729, 21.037)
  point P10 (29.5, -2.675)
  point P38 (29.5, -2.675)
  coincident P12 P17
  coincident P7 P18
  midpoint L9 P19
  perpendicular L9 L10
  vertical L13
  perpendicular L13 L14
  coincident P20 P22
  concentric C3 C4
  concentric A1 C5
  coincident P17 P25
  coincident P22 P26
  coincident C4 P27
  perpendicular L12 L15
  coincident P22 P28
  coincident C4 P29
  perpendicular L12 L16
  coincident C6 P30
  tangent C6 L17
  coincident P12 P31
  coincident P25 P32
  coincident C6 P33
  collinear L18 L19
  coincident L17 P34
  coincident L20 P35
  perpendicular L20 L21
  coincident L17 P36
  coincident L20 P37
  perpendicular L20 L22
  coincident P10 P38
  dimension "d263" distance P19 P20 = 26
  dimension "d264" diameter C3 = 3.3
  dimension "d265" diameter C4 = 9.2
  dimension "d266" diameter C5 = 9.2
  dimension "d267" diameter C6 = 9.2
  dimension "d268" distance P31 L21 = 5.6 (= "( 9.2 / 2 ) * 1 mm + 1 mm")
  dimension "d269" distance L15 L22 = 5.6
  dimension "d277" angle L12 L23 = 99.667
extrude "Extrude33" sketch "Sketch22" profile of C2 C3 C4 C6 L17 L20 L21 L22 to an object offset 0.2 from offset -0.2
extrude "Extrude34" sketch "Sketch22" profile of C2 C3 C4 C6 L17 L20 L21 L22 to an object offset 0.2 from offset -0.2
move "Move5"
move "Move9"
move "Move10"
offset_faces "OffsetFaces26" distance -0.4
sketch "Sketch24" plane through (0, 0, 0) normal (1, 0, 0) x axis (0, 1, 0)
  line L1 (33.9713, 21.6316) -> (43.0398, 20.0815)
  line L2 (34.8137, 26.5601) -> (33.9713, 21.6316)
  line L3 (43.0398, 20.0815) -> (43.8822, 25.01)
  line L4 (39.0347, -3.4475) -> (39.9751, 2.073)
  line L5 (30.9057, 3.6179) -> (29.9653, -1.9025)
  line L6 (39.9751, 2.073) -> (30.9057, 3.6179)
  line L7 (30.9057, 3.6179) -> (33.9713, 21.6316)
  line L8 (39.9751, 2.073) -> (43.0398, 20.0815)
  line L9 (41.5074, 11.0772) -> (34.5, -2.675)
  line L10 (32.4385, 12.6247) -> (34.5, -2.675)
  circle C1 centre (39.348, 25.785) radius 1.65
  arc A1 centre (39.348, 25.785) radius 4.6 clockwise from (34.8137, 26.5601) to (43.8822, 25.01)
  circle C2 centre (34.5, -2.675) radius 1.65
  arc A2 centre (34.5, -2.675) radius 4.6 clockwise from (39.0347, -3.4475) to (29.9653, -1.9025)
  arc A3 centre (34.5, -2.675) radius 5 clockwise from (29.5, -2.675) to (39.5, -2.675)
  circle C3 centre (34.5, -2.675) radius 8
  point P4 (33.9713, 21.6316)
  point P12 (33.9713, 21.6316)
  point P11 (30.9057, 3.6179)
  point P13 (30.9057, 3.6179)
  point P3 (43.0398, 20.0815)
  point P14 (43.0398, 20.0815)
  point P8 (39.9751, 2.073)
  point P15 (39.9751, 2.073)
  point P18 (34.5, -2.675)
  point P19 (34.5, -2.675)
  point P20 (41.5074, 11.0772)
  point P21 (34.5, -2.675)
  point P22 (32.4385, 12.6247)
  point P23 (34.5, -2.675)
  coincident P4 P12
  coincident P11 P13
  coincident P3 P14
  coincident P8 P15
  coincident P18 P19
  midpoint L8 P20
  coincident P18 P21
  midpoint L7 P22
  coincident P21 P23
  dimension "d314" diameter C3 = 16
extrude "Extrude39" sketch "Sketch24" profile of L1 L6 L7 L8 to an object
extrude "Extrude40" sketch "Sketch24" profile of L6 L7 L8 L9 L10 C3 to an object
extrude "Extrude41" sketch "Sketch24" profile of L6 L7 L8 L9 L10 C3 to an object
sketch "Sketch25" plane through (0, 1.4704, 8.632) normal (0, -0.1679, -0.9858) x axis (1, 0, 0)
  line L1 (11.825, -29.8579) -> (11.825, -32.0748)
  line L2 (9.725, -29.8579) -> (11.825, -29.8579)
  line L3 (9.725, -32.0748) -> (9.725, -29.8579)
  line L4 (11.825, -36.8428) -> (11.825, -39.0579)
  line L5 (9.725, -39.0579) -> (9.725, -36.8428)
  line L6 (11.825, -39.0579) -> (9.725, -39.0579)
  line L7 (19.725, -36.8428) -> (19.725, -39.0579)
  line L8 (17.625, -39.0579) -> (17.625, -36.8428)
  line L9 (19.725, -39.0579) -> (17.625, -39.0579)
  line L10 (19.725, -29.8579) -> (19.725, -32.0748)
  line L11 (17.625, -29.8579) -> (19.725, -29.8579)
  line L12 (17.625, -32.0748) -> (17.625, -29.8579)
  line L13 (11.825, -29.9748) -> (9.725, -32.0748)
  line L14 (12.6948, -32.0748) -> (9.725, -32.0748)
  line L15 (17.625, -29.9748) -> (19.725, -32.0748)
  line L16 (17.625, -38.9428) -> (19.725, -36.8428)
  line L17 (11.825, -38.9428) -> (9.725, -36.8428)
  line L18 (11.825, -32.0748) -> (9.725, -32.0748)
  line L19 (9.725, -36.8428) -> (11.825, -36.8428)
  line L20 (17.625, -36.8428) -> (19.725, -36.8428)
  line L21 (19.725, -32.0748) -> (17.625, -32.0748)
  point P5 (9.725, -32.0748)
  point P18 (9.725, -32.0748)
  point P19 (11.825, -29.9748)
  point P14 (19.725, -32.0748)
  point P21 (19.725, -32.0748)
  point P22 (17.625, -29.9748)
  point P11 (19.725, -36.8428)
  point P23 (19.725, -36.8428)
  point P24 (17.625, -38.9428)
  point P8 (9.725, -36.8428)
  point P25 (9.725, -36.8428)
  point P26 (11.825, -38.9428)
  horizontal L14
  coincident P5 P18
  coincident L1 P19
  coincident P14 P21
  coincident L12 P22
  coincident P11 P23
  coincident L8 P24
  coincident P8 P25
  coincident L4 P26
  perpendicular L16 L17
  dimension "d310" angle L13 L14 = 45
  dimension "d311" angle L13 L15 = 90
  dimension "d312" angle L15 L16 = 90
sketch "Sketch26" plane through (0, 4.557, 26.6594) normal (0, 0.1685, 0.9857) x axis (-1, 0, 0)
  line L1 (-15.625, -29.8409) -> (-15.625, -39.0409)
  line L2 (-17.825, -29.8409) -> (-15.625, -29.8409)
  line L3 (-17.825, -39.0409) -> (-17.825, -29.8409)
  line L4 (-15.625, -39.0409) -> (-17.825, -39.0409)
loft "Loft1" sketch "Sketch25"
delete_face "DeleteFace14"
loft "Loft2" sketch "Sketch25"
delete_face "DeleteFace15"
delete_face "DeleteFace16"
loft "Loft3" sketch "Sketch25"
delete_face "DeleteFace17"
delete_face "DeleteFace18"
loft "Loft4" sketch "Sketch25"
delete_face "DeleteFace19"
chamfer "Chamfer17" distance 2.1 distance 2.1 distance 2.1 distance 2.1
sketch "Sketch27" plane through (9.725, 0, 0) normal (-1, 0, 0) x axis (0, -1, 0)
  line L1 (-34.8137, 26.5601) -> (-33.9713, 21.6316)
  line L2 (-43.0398, 20.0815) -> (-43.8822, 25.01)
  line L3 (-33.9713, 21.6316) -> (-43.0398, 20.0815)
  line L4 (-33.3411, 20.319) -> (-43.1982, 18.6341)
  line L5 (-33.9713, 21.6316) -> (-33.2866, 7.3519)
  line L6 (-38.9629, 6.3855) -> (-43.0398, 20.0815)
  line L7 (-38.9629, 6.3855) -> (-43.0398, 20.0815)
  line L8 (-33.9713, 21.6316) -> (-33.2866, 7.3519)
  line L9 (-36.1937, 26.3242) -> (-35.3656, 21.4795)
  line L10 (-41.6739, 20.4003) -> (-42.5022, 25.2459)
  line L11 (-38.0602, 8.26) -> (-41.6739, 20.4003)
  line L12 (-35.3656, 21.4795) -> (-34.7587, 8.8221)
  arc A1 centre (-39.348, 25.785) radius 4.6 clockwise from (-43.8822, 25.01) to (-34.8137, 26.5601)
  circle C1 centre (-39.348, 25.785) radius 1.65
  arc A2 centre (-34.5, -2.675) radius 10.1 clockwise from (-38.9629, 6.3855) to (-33.2866, 7.3519)
  arc A3 centre (-39.348, 25.785) radius 3.2 clockwise from (-42.5022, 25.2459) to (-36.1937, 26.3242)
  arc A4 centre (-34.5, -2.675) radius 11.5 clockwise from (-38.0602, 8.26) to (-34.7587, 8.8221)
  arc A5 centre (-34.5, -2.675) radius 10.1 clockwise from (-38.9629, 6.3855) to (-33.2866, 7.3519)
  dimension "d302" = -1.4
  dimension "d303" = 1.4
extrude "Extrude42" cut sketch "Sketch27" profile of L4 L12 L11 A4 against normal blind 0.8 taper -45
extrude "Extrude43" sketch "Sketch27" profile of L4 L12 L11 A4 blind 0.8 taper -45
sketch "Sketch28" plane through (9.725, 0, 0) normal (-1, 0, 0) x axis (0, -1, 0)
  line L1 (-41.2475, 18.9675) -> (-38.0602, 8.26)
  line L2 (-34.8137, 26.5601) -> (-33.9713, 21.6316)
  line L3 (-43.0398, 20.0815) -> (-43.8822, 25.01)
  line L4 (-38.9629, 6.3855) -> (-43.0398, 20.0815)
  line L5 (-33.9713, 21.6316) -> (-43.0398, 20.0815)
  line L6 (-38.5055, 20.8565) -> (-39.348, 25.785)
  line L7 (-43.0398, 20.0815) -> (-41.5074, 11.0772)
  line L8 (-32.4385, 12.6247) -> (-33.9713, 21.6316)
  line L9 (-42.2736, 15.5794) -> (-33.2049, 17.1282)
  line L10 (-37.7392, 16.3538) -> (-38.5055, 20.8565)
  line L11 (-33.1378, 16.7338) -> (-38.3378, 19.8707)
  line L12 (-42.2074, 15.1903) -> (-38.3378, 19.8707)
  line L13 (-39.9751, 2.073) -> (-30.9057, 3.6179)
  line L14 (-30.9057, 3.6179) -> (-29.9653, -1.9025)
  line L15 (-30.9057, 3.6179) -> (-32.4385, 12.6247)
  line L16 (-39.0347, -3.4475) -> (-39.9751, 2.073)
  line L17 (-41.5074, 11.0772) -> (-39.9751, 2.073)
  line L18 (-35.4404, 2.8455) -> (-37.7392, 16.3538)
  line L19 (-31.6388, 7.9259) -> (-35.5075, 3.2398)
  line L20 (-40.7084, 6.3824) -> (-35.5075, 3.2398)
  arc A1 centre (-34.5, -2.675) radius 11.5 clockwise from (-38.0602, 8.26) to (-34.7587, 8.8221)
  arc A2 centre (-34.5, -2.675) radius 10.1 clockwise from (-38.9629, 6.3855) to (-33.2866, 7.3519)
  arc A3 centre (-39.348, 25.785) radius 4.6 clockwise from (-43.8822, 25.01) to (-34.8137, 26.5601)
  circle C1 centre (-39.348, 25.785) radius 1.65
  point P11 (-39.348, 25.785)
  point P15 (-39.348, 25.785)
  point P16 (-38.5055, 20.8565)
  point P21 (-33.2049, 17.1282)
  point P22 (-42.2736, 15.5794)
  point P23 (-37.7392, 16.3538)
  point P24 (-38.3378, 19.8707)
  point P25 (-33.1378, 16.7338)
  point P26 (-38.3378, 19.8707)
  point P27 (-42.2074, 15.1903)
  point P36 (-35.4404, 2.8455)
  point P37 (-35.5075, 3.2398)
  point P38 (-31.6388, 7.9259)
  point P39 (-35.5075, 3.2398)
  point P40 (-40.7084, 6.3824)
  coincident P11 P15
  midpoint L5 P16
  midpoint L8 P21
  midpoint L7 P22
  midpoint L9 P23
  coincident L10 P24
  coincident L8 P25
  symmetric L10 P24 P26
  symmetric L10 P25 P27
  midpoint L13 P36
  coincident L18 P37
  coincident L15 P38
  symmetric L18 P37 P39
  symmetric L18 P38 P40
  dimension "d325" distance P16 P24 = 1
  dimension "d326" distance P21 P25 = 0.4
  dimension "d330" distance P36 P37 = 0.4
  dimension "d331" angle L18 L19 = 49.2
extrude "Extrude44" sketch "Sketch28" profile of L4 L5 L7 L8 L11 L12 to an object
extrude "Extrude45" sketch "Sketch28" profile of L4 L5 L7 L8 L11 L12 to an object
chamfer "Chamfer18" distance 1 distance 1
chamfer "Chamfer19" distance 1
extrude "Extrude46" sketch "Sketch28" profile of L13 L15 L17 L19 L20 to an object
chamfer "Chamfer20" distance 1
copy_paste_bodies "CopyPasteBodies3"
move "Move11"
move "Move13"
move "Move14"
move "Move15"
remove_body "RemoveBody5"
remove_body "RemoveBody6"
